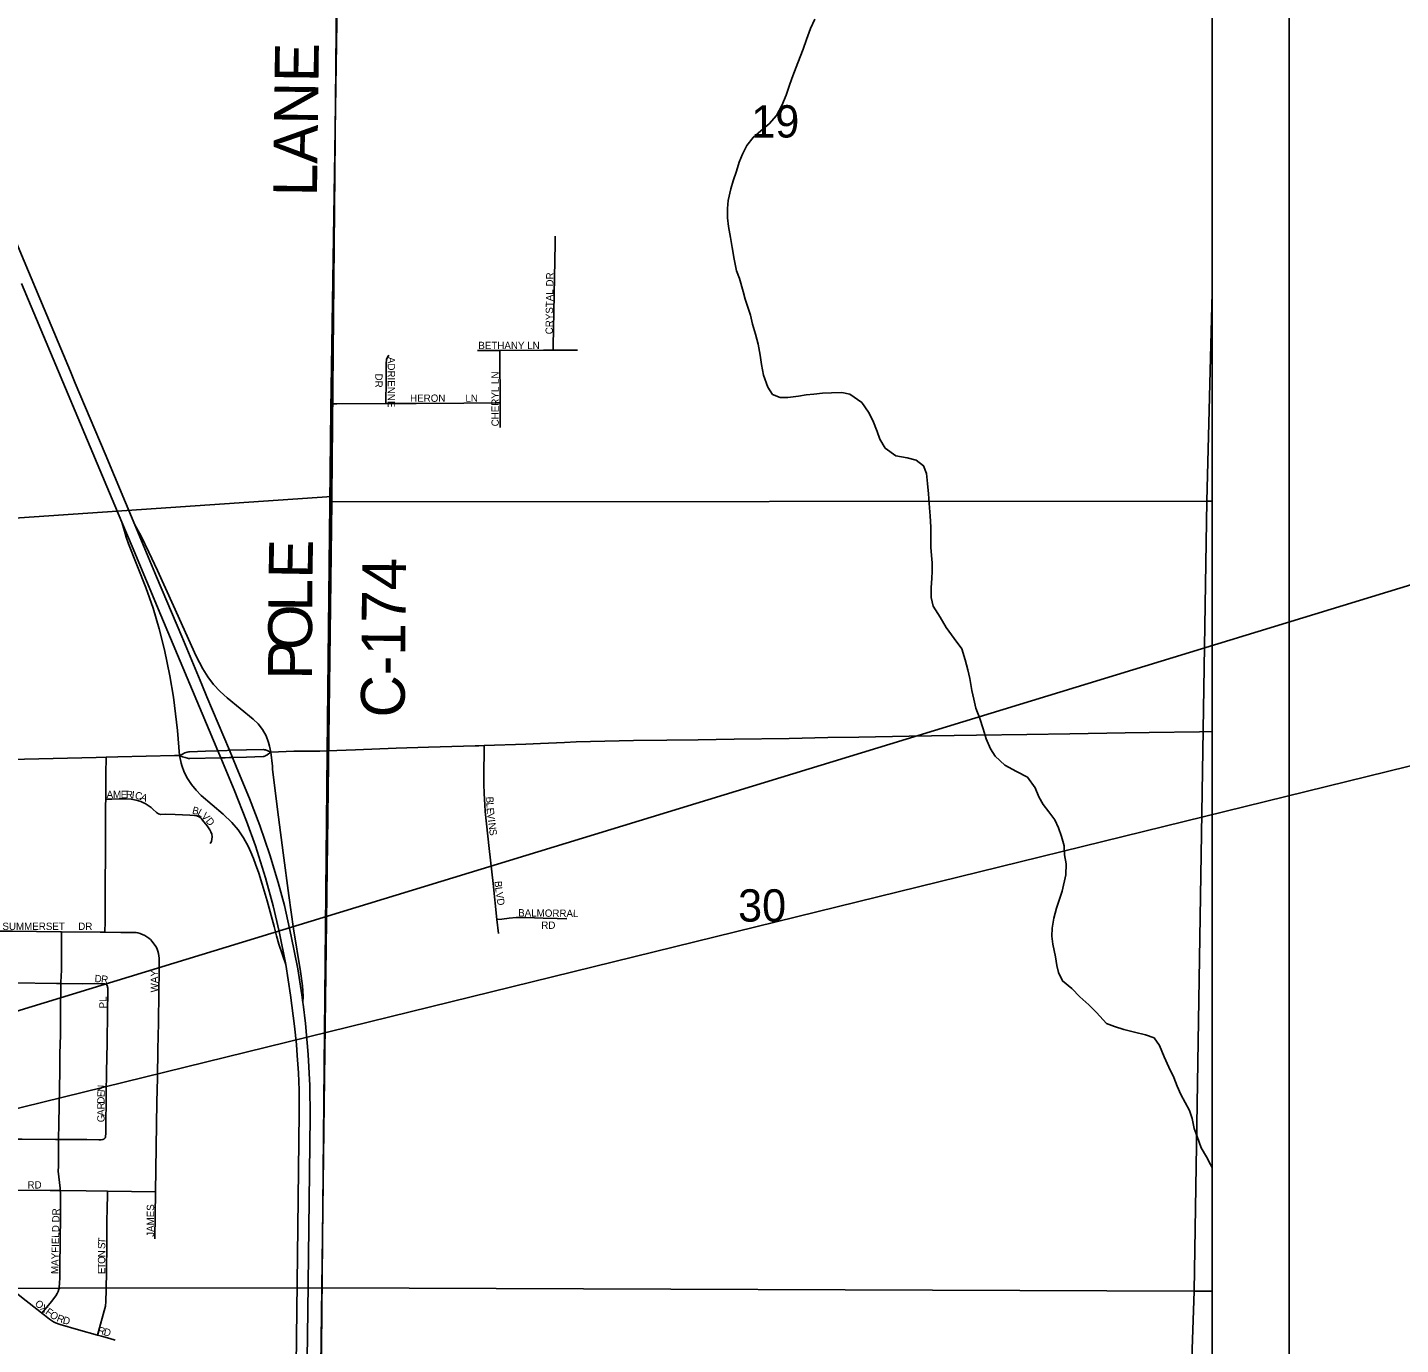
# Model space of a CAD drawing. Extents: x -9.1 to 34, y -3.1 to 22.
# Drawn here: x 7.865 to 9.644, y 18.681 to 20.388 of the extents above; entities that cross this region are included whole.
import ezdxf

# ---------------------------------------------------------------- set-up
doc = ezdxf.new("R2010")
doc.units = 0
for name, color, linetype in [('GM_X_County_Road', 7, 'Continuous'), ('GM_X_County_Road_Text', 7, 'Continuous'), ('GM_X_Interchange_Ramps', 7, 'Continuous'), ('GM_X_Minor_River', 7, 'Continuous'), ('GM_X_Section', 7, 'Continuous'), ('GM_X_Section_Text', 7, 'Continuous'), ('GM_X_State_Route', 7, 'Continuous'), ('GM_X_Township', 7, 'Continuous'), ('GM_X_Township_Subdivision', 7, 'Continuous'), ('GM_X_Township_Subdivision_Text', 7, 'Continuous'), ('GM_X_US_Route', 7, 'Continuous'), ('SH_Data', 7, 'Continuous'), ('SH_Text', 7, 'Continuous')]:
    doc.layers.add(name, color=color, linetype=linetype)

msp = doc.modelspace()

# ---------------------------------------------------------------- linework, layer by layer
at = {"layer": 'GM_X_County_Road'}
for points in [[(8.2593, 19.9003), (8.2605, 19.9991), (8.261, 20.0209), (8.2609, 20.0489), (8.2612, 20.0551), (8.2618, 20.0924), (8.263, 20.1949), (8.2641, 20.2889), (8.2658, 20.4372), (8.2662, 20.4625)], [(8.2539, 19.4505), (8.254, 19.4543), (8.2552, 19.5829), (8.2556, 19.6078), (8.2562, 19.6482), (8.2568, 19.7072), (8.2571, 19.7383), (8.2577, 19.7787), (8.2587, 19.8563), (8.2593, 19.9003)]]:
    msp.add_lwpolyline(points, dxfattribs=at)
at = {"layer": 'GM_X_Interchange_Ramps'}
for points in [[(7.9874, 19.7467), (7.9906, 19.7351), (7.9928, 19.7274), (7.996, 19.7187), (8.0185, 19.662), (8.0277, 19.6355), (8.0357, 19.6086), (8.0425, 19.5813), (8.0495, 19.5477), (8.0541, 19.5201), (8.0594, 19.4767), (8.0622, 19.4446)], [(8.1802, 19.4488), (8.1785, 19.4565), (8.1773, 19.4612), (8.1742, 19.4699), (8.1697, 19.478), (8.164, 19.4853), (8.1573, 19.4917), (8.1405, 19.5055), (8.1237, 19.5191), (8.1146, 19.5275), (8.1062, 19.5365), (8.0987, 19.5463), (8.0921, 19.5568), (8.0835, 19.5733), (8.0542, 19.6382), (8.0336, 19.6841), (8.0224, 19.7081), (8.0125, 19.7287), (8.004, 19.7435)], [(8.222, 19.1242), (8.2223, 19.1327), (8.2214, 19.1459), (8.219, 19.1647), (8.2096, 19.2198), (8.2038, 19.2629), (8.1964, 19.3184), (8.1901, 19.3646), (8.1827, 19.4263), (8.1823, 19.4306), (8.1802, 19.4488)], [(8.0622, 19.4446), (8.0637, 19.4368), (8.0642, 19.4345), (8.065, 19.4317), (8.0682, 19.4229), (8.0724, 19.4146), (8.0776, 19.4067), (8.0835, 19.3994), (8.0901, 19.3927), (8.1187, 19.3685), (8.1298, 19.3575), (8.1378, 19.348), (8.1449, 19.3377), (8.151, 19.3269), (8.1544, 19.3193), (8.1578, 19.3111), (8.1605, 19.3038), (8.1647, 19.292), (8.1692, 19.278), (8.1758, 19.2563), (8.1848, 19.2231), (8.1876, 19.211), (8.1906, 19.2001), (8.1996, 19.1737)]]:
    msp.add_lwpolyline(points, dxfattribs=at)
at = {"layer": 'GM_X_Minor_River'}
for points in [[(8.8851, 20.3984), (8.8798, 20.3863), (8.8744, 20.3723), (8.8702, 20.3595), (8.8664, 20.3496), (8.861, 20.3364), (8.8568, 20.325), (8.853, 20.3144), (8.848, 20.3), (8.8426, 20.2868), (8.8358, 20.2736), (8.8259, 20.263), (8.8152, 20.2539), (8.8053, 20.2452), (8.7973, 20.2347), (8.7916, 20.2237), (8.787, 20.2131), (8.7836, 20.2017), (8.7793, 20.1889), (8.7763, 20.1786), (8.7728, 20.1635), (8.772, 20.1533), (8.7723, 20.1411), (8.7734, 20.1298), (8.776, 20.1157), (8.7783, 20.1025), (8.7808, 20.0877), (8.7838, 20.0725), (8.7876, 20.0626), (8.7924, 20.0456), (8.7951, 20.0357)], [(8.7951, 20.0357), (8.7984, 20.0254), (8.8018, 20.0148), (8.8044, 20.0031), (8.8085, 19.9902), (8.8119, 19.9776), (8.8145, 19.9632), (8.8163, 19.9511), (8.8189, 19.9374), (8.8242, 19.9219), (8.8306, 19.9124), (8.8404, 19.9082), (8.8503, 19.9085), (8.8639, 19.91), (8.8742, 19.9118), (8.884, 19.9126), (8.895, 19.914), (8.9068, 19.9144), (8.9201, 19.9147), (8.9307, 19.9128), (8.9462, 19.9017), (8.9548, 19.8895), (8.9605, 19.8785), (8.9661, 19.8641), (8.9695, 19.8542), (8.9763, 19.8428), (8.9903, 19.8329), (9.0047, 19.8302), (9.0164, 19.8272), (9.0262, 19.8199), (9.03, 19.8097), (9.0314, 19.7968), (9.0325, 19.7835), (9.034, 19.7653), (9.0347, 19.7551), (9.0354, 19.7403), (9.0357, 19.7289), (9.0357, 19.7145), (9.0364, 19.7035), (9.0371, 19.694), (9.0375, 19.6834), (9.037, 19.674), (9.0362, 19.6622), (9.0362, 19.6493), (9.0388, 19.6379), (9.0475, 19.6235), (9.0554, 19.6102), (9.0656, 19.5961), (9.0757, 19.5825), (9.0802, 19.5684), (9.0836, 19.5555), (9.0862, 19.5441), (9.0888, 19.5286), (9.0914, 19.5176), (9.094, 19.5058), (9.0989, 19.4925), (9.1034, 19.4789), (9.1071, 19.466), (9.1128, 19.4531), (9.1188, 19.4436), (9.1316, 19.4318), (9.1468, 19.4238), (9.1608, 19.4165), (9.1706, 19.4024), (9.1755, 19.3911), (9.1811, 19.3812), (9.1883, 19.3717), (9.1962, 19.361), (9.2011, 19.3508), (9.2048, 19.3394), (9.2082, 19.3273), (9.2089, 19.3159), (9.2108, 19.3041), (9.2107, 19.2897), (9.2057, 19.2689), (9.2023, 19.2583), (9.1984, 19.2469), (9.195, 19.2337), (9.193, 19.2208), (9.1922, 19.2106), (9.1937, 19.2), (9.197, 19.1836), (9.1989, 19.1726), (9.2011, 19.1632), (9.2064, 19.1525), (9.2185, 19.1426), (9.2287, 19.132), (9.2404, 19.1213), (9.2502, 19.1114), (9.2631, 19.0974), (9.2737, 19.0935), (9.2858, 19.0897), (9.2994, 19.0862), (9.3138, 19.0828), (9.3248, 19.0785), (9.3319, 19.0687), (9.3379, 19.0539), (9.344, 19.0406), (9.3504, 19.0273), (9.3549, 19.0159), (9.3594, 19.0053)], [(9.3594, 19.0053), (9.365, 18.995), (9.3707, 18.9844), (9.3744, 18.9741), (9.377, 18.9612), (9.3808, 18.951), (9.386, 18.9362), (9.3928, 18.9244), (9.3981, 18.9145), (9.4, 18.9105)]]:
    msp.add_lwpolyline(points, dxfattribs=at)
at = {"layer": 'GM_X_Section'}
for p, q in [((9.4, 20.0439), (9.4, 20.782)), ((9.4, 19.7739), (9.4, 20.0439)), ((9.4, 18.7507), (9.4, 19.7739)), ((9.4, 17.736), (9.4, 18.7507))]:
    msp.add_line(p, q, dxfattribs=at)
for points in [[(9.4, 20.782), (8.2692, 20.7856), (8.2683, 20.7561), (8.2596, 19.7802), (8.2596, 19.773), (9.3932, 19.7739), (9.4, 20.0439)], [(9.4, 20.0439), (9.3932, 19.7739), (9.4, 19.7739)], [(9.4, 19.7739), (9.3932, 19.7739), (9.3766, 18.7507), (9.4, 18.7507)], [(9.4, 18.7507), (9.3766, 18.7507), (9.3419, 17.736), (9.4, 17.736)]]:
    msp.add_lwpolyline(points, dxfattribs=at)
for points in [[(8.2683, 20.7561), (8.2596, 19.7802), (7.2408, 19.7107), (7.2498, 20.7358)], [(8.2596, 19.7802), (8.2596, 19.773), (8.2465, 18.7547), (7.2285, 18.7534), (7.2408, 19.7107)], [(9.3932, 19.7739), (9.3766, 18.7507), (8.2465, 18.7547), (8.2596, 19.773)], [(7.2285, 18.7534), (8.2465, 18.7547), (8.2334, 17.7485), (7.2227, 17.7567)], [(9.3766, 18.7507), (9.3419, 17.736), (8.2334, 17.7485), (8.2465, 18.7547)]]:
    msp.add_lwpolyline(points, close=True, dxfattribs=at)
at = {"layer": 'GM_X_State_Route'}
for points in [[(8.5299, 19.46), (8.5609, 19.4613), (8.5759, 19.4621), (8.6501, 19.4638), (8.6936, 19.4643), (8.734, 19.4649), (8.7806, 19.4655), (8.8521, 19.4667), (8.9019, 19.4677), (8.9423, 19.4684), (9.0076, 19.4695), (9.0946, 19.4707), (9.1599, 19.4716), (9.2158, 19.4726), (9.2873, 19.4737), (9.3184, 19.4741), (9.3837, 19.4751), (9.4, 19.4754)], [(8.0622, 19.4446), (8.0657, 19.4464), (8.069, 19.4478), (8.0719, 19.4489), (8.0737, 19.4492), (8.075, 19.4494), (8.0957, 19.4501), (8.1117, 19.4507), (8.1238, 19.4511), (8.1269, 19.4512), (8.1707, 19.4522), (8.1722, 19.452), (8.1734, 19.4517), (8.1745, 19.4513), (8.1755, 19.451), (8.1802, 19.4488)], [(8.1267, 19.4418), (8.1308, 19.4419), (8.1487, 19.4425), (8.1704, 19.4432), (8.1713, 19.4434), (8.1725, 19.4437), (8.1739, 19.4443), (8.175, 19.4449), (8.1757, 19.4454), (8.1802, 19.4488), (8.2101, 19.4499), (8.244, 19.4502), (8.2539, 19.4505)], [(8.2539, 19.4505), (8.29, 19.4517), (8.3429, 19.4538), (8.3846, 19.4553), (8.4452, 19.457), (8.4499, 19.4572)], [(8.4499, 19.4572), (8.4569, 19.4574), (8.5106, 19.4592), (8.5299, 19.46)], [(7.7873, 19.4379), (7.7905, 19.438), (7.8426, 19.4392), (7.9538, 19.4418), (7.967, 19.4423), (7.9821, 19.4429), (8.0553, 19.4445)], [(8.0553, 19.4445), (8.0622, 19.4446)], [(8.0622, 19.4446), (8.0659, 19.4428), (8.0693, 19.4417), (8.0723, 19.4409), (8.0738, 19.4407), (8.0755, 19.4406), (8.1156, 19.4415), (8.1213, 19.4416), (8.1267, 19.4418)]]:
    msp.add_lwpolyline(points, dxfattribs=at)
at = {"layer": 'GM_X_Township'}
for points in [[(8.2717, 20.9), (8.2689, 20.7443), (8.2697, 20.6456), (8.2583, 19.8928), (8.2535, 19.4485), (8.2445, 18.5434), (8.2345, 17.7477), (8.5348, 17.7425), (9.3398, 17.7284), (9.4, 17.7292)], [(9.4, 17.7292), (9.4, 20.9), (8.2717, 20.9)]]:
    msp.add_lwpolyline(points, dxfattribs=at)
at = {"layer": 'GM_X_Township_Subdivision'}
for points in [[(8.5463, 19.9695), (8.5464, 19.9752), (8.5487, 20.1076), (8.5489, 20.1171)], [(8.4482, 19.9691), (8.477, 19.9692)], [(8.477, 19.9692), (8.5337, 19.9695), (8.5463, 19.9695)], [(8.4773, 19.9014), (8.4771, 19.9629), (8.477, 19.9692)], [(8.5463, 19.9695), (8.5777, 19.9696)], [(8.3293, 19.9005), (8.3296, 19.9309), (8.3299, 19.9542), (8.3301, 19.9559), (8.3304, 19.9576), (8.3316, 19.9607), (8.3332, 19.963)], [(8.2593, 19.9003), (8.266, 19.9003), (8.3293, 19.9005)], [(8.3293, 19.9005), (8.3685, 19.9007), (8.4306, 19.9009), (8.471, 19.9013), (8.4773, 19.9014)], [(8.4774, 19.8693), (8.4773, 19.9014)], [(8.4564, 19.4154), (8.4564, 19.4288), (8.4567, 19.4441), (8.4569, 19.4574)], [(7.9664, 19.3879), (7.9665, 19.3984), (7.9665, 19.4055), (7.9666, 19.4276), (7.9668, 19.4356), (7.967, 19.4423)], [(8.4632, 19.3242), (8.4582, 19.3719), (8.4576, 19.3806), (8.4569, 19.3952), (8.4564, 19.4074), (8.4564, 19.4154)], [(7.9653, 19.2154), (7.9657, 19.2293), (7.9657, 19.2332), (7.9657, 19.262), (7.9658, 19.2722), (7.9658, 19.2866), (7.9659, 19.3086), (7.9661, 19.3498), (7.9662, 19.3609), (7.9663, 19.3797), (7.9664, 19.3879)], [(7.9664, 19.3879), (7.9745, 19.3881), (7.9839, 19.3884), (7.9933, 19.3884), (7.9995, 19.3879), (8.0057, 19.3867), (8.0117, 19.3849), (8.0145, 19.3836), (8.0173, 19.3822), (8.02, 19.3806), (8.0252, 19.377), (8.0275, 19.3749), (8.032, 19.3705), (8.0346, 19.3689), (8.0376, 19.3682), (8.0439, 19.3683), (8.0564, 19.3682), (8.0752, 19.3674), (8.0815, 19.3669), (8.0846, 19.3663), (8.0874, 19.365), (8.0899, 19.3631), (8.092, 19.3609), (8.0978, 19.3534), (8.1013, 19.3482), (8.1027, 19.3454), (8.1037, 19.3424), (8.1042, 19.3393), (8.1041, 19.3362), (8.1033, 19.3332), (8.1019, 19.3304)], [(8.4734, 19.2318), (8.4683, 19.2785), (8.4632, 19.3242)], [(8.4734, 19.2318), (8.4798, 19.2326), (8.4891, 19.2338), (8.4984, 19.2345), (8.5109, 19.2346), (8.5332, 19.2339)], [(8.5332, 19.2339), (8.5515, 19.2332), (8.5632, 19.233), (8.5636, 19.2331), (8.564, 19.2333)], [(7.7817, 19.217), (7.7961, 19.217), (7.8045, 19.2171), (7.8148, 19.217), (7.8458, 19.2167), (7.8769, 19.2165), (7.9079, 19.2162), (7.9092, 19.2162)], [(7.9084, 19.1491), (7.9084, 19.151), (7.9089, 19.1665), (7.9092, 19.1945), (7.9092, 19.2068), (7.9092, 19.2162)], [(7.9092, 19.2162), (7.9591, 19.2156), (7.9653, 19.2154)], [(8.4753, 19.2138), (8.4734, 19.2318)], [(7.9653, 19.2154), (7.9859, 19.2153), (8.0019, 19.2153), (8.0029, 19.2153)], [(8.0355, 19.1654), (8.0358, 19.1757), (8.0356, 19.1819), (8.0354, 19.1849), (8.0349, 19.1879), (8.0341, 19.1908), (8.0331, 19.1937), (8.0318, 19.1964), (8.0302, 19.1989), (8.0265, 19.2037), (8.0243, 19.2059), (8.0221, 19.2079), (8.0196, 19.2096), (8.017, 19.2111), (8.0142, 19.2124), (8.0126, 19.2131), (8.011, 19.2137), (8.0079, 19.2148), (8.0057, 19.2151), (8.0029, 19.2153)], [(8.031, 18.879), (8.0327, 18.9953), (8.0333, 19.0268), (8.0339, 19.0637), (8.0346, 19.098), (8.0351, 19.1378), (8.0355, 19.1654)], [(7.8453, 19.1501), (7.847, 19.1501), (7.9026, 19.1492), (7.9084, 19.1491)], [(7.9052, 18.947), (7.9056, 18.9677), (7.9069, 19.036), (7.9069, 19.0485), (7.907, 19.0578), (7.9077, 19.0826), (7.9077, 19.0981), (7.908, 19.1106), (7.9084, 19.1491)], [(7.9084, 19.1491), (7.9365, 19.1488), (7.9519, 19.1489), (7.9615, 19.1488), (7.9646, 19.1485), (7.9661, 19.1481), (7.9672, 19.1476)], [(7.9648, 18.9481), (7.9653, 18.9486), (7.9657, 18.9493), (7.9659, 18.9502), (7.9662, 18.9515), (7.9664, 18.9545), (7.9664, 18.972), (7.9668, 18.9938), (7.9669, 19.0063), (7.9673, 19.0345), (7.9681, 19.072), (7.9687, 19.1126), (7.9692, 19.1386), (7.9691, 19.1429), (7.9689, 19.1443), (7.9686, 19.1456), (7.968, 19.1468), (7.9672, 19.1476)], [(7.842, 18.9476), (7.8581, 18.9475), (7.9015, 18.947), (7.9052, 18.947)], [(7.905, 18.9129), (7.905, 18.9211), (7.9051, 18.9397), (7.9052, 18.947)], [(7.9052, 18.947), (7.9418, 18.9468), (7.9573, 18.9466), (7.9607, 18.9467), (7.9628, 18.9471), (7.964, 18.9475), (7.9648, 18.9481)], [(7.9075, 18.881), (7.9072, 18.884), (7.9055, 18.8986), (7.9051, 18.9027), (7.9049, 18.9056), (7.905, 18.9129)], [(7.8491, 18.8814), (7.8512, 18.8813), (7.8946, 18.8811), (7.9075, 18.881)], [(7.8837, 18.7218), (7.8881, 18.7273), (7.896, 18.737), (7.9016, 18.7445), (7.9033, 18.7473), (7.9046, 18.7502), (7.9055, 18.7533), (7.9061, 18.7564), (7.9065, 18.7596), (7.9069, 18.7689), (7.907, 18.7814), (7.9075, 18.8158), (7.9079, 18.8467), (7.908, 18.859), (7.908, 18.8684), (7.9079, 18.8778), (7.9075, 18.881)], [(7.9075, 18.881), (7.9411, 18.8806), (7.9687, 18.8802)], [(7.9557, 18.6936), (7.957, 18.6984), (7.9645, 18.7251), (7.9659, 18.7311), (7.9667, 18.7371), (7.967, 18.7524), (7.9673, 18.777), (7.9678, 18.8109), (7.968, 18.8386), (7.9684, 18.8602), (7.9686, 18.8725), (7.9687, 18.8802)], [(7.9687, 18.8802), (8.031, 18.879)], [(8.0299, 18.8181), (8.031, 18.879)], [(7.8837, 18.7218), (7.8808, 18.7241), (7.8596, 18.7412), (7.8343, 18.7613)], [(7.9557, 18.6936), (7.9311, 18.7005), (7.9072, 18.7074), (7.9014, 18.7094), (7.8987, 18.7107), (7.8936, 18.7141), (7.887, 18.7193), (7.8837, 18.7218)], [(7.9786, 18.6871), (7.9718, 18.6891), (7.9611, 18.6921), (7.9557, 18.6936)]]:
    msp.add_lwpolyline(points, dxfattribs=at)
at = {"layer": 'GM_X_US_Route'}
for points in [[(7.9207, 19.9418), (7.8955, 20.0014), (7.8607, 20.0848), (7.8464, 20.1189), (7.8172, 20.1875), (7.7752, 20.2878), (7.7605, 20.3227)], [(8.2128, 18.6185), (8.2154, 18.8328), (8.2169, 18.982), (8.217, 19.0111), (8.2163, 19.0333), (8.2145, 19.056), (8.2134, 19.07), (8.211, 19.0938), (8.206, 19.1339), (8.1996, 19.1737), (8.1996, 19.1738), (8.1912, 19.2165), (8.1833, 19.2498), (8.1734, 19.2858), (8.1604, 19.3274), (8.1489, 19.3596), (8.1328, 19.4), (8.1156, 19.4415), (8.1117, 19.4507), (8.1006, 19.4775), (8.0379, 19.6264), (8.0006, 19.7152), (7.9874, 19.7467), (7.8572, 20.0561)], [(8.1364, 19.4282), (8.1308, 19.4419), (8.1269, 19.4512), (8.0976, 19.5205), (8.091, 19.5364), (8.0651, 19.5987), (8.0323, 19.6761), (8.004, 19.7435), (7.9655, 19.8353), (7.927, 19.9269), (7.9207, 19.9418)], [(8.2222, 19.1222), (8.222, 19.1242), (8.2207, 19.1343), (8.2153, 19.168), (8.2069, 19.2106), (8.198, 19.25), (8.19, 19.28), (8.1791, 19.3156), (8.1661, 19.3538), (8.1528, 19.3886), (8.1364, 19.4282)], [(8.2176, 17.8023), (8.2192, 17.939), (8.2198, 17.9855), (8.2201, 18.0166), (8.223, 18.2465), (8.2235, 18.2962), (8.2251, 18.4174), (8.2262, 18.5262), (8.2265, 18.5511), (8.2266, 18.5664), (8.2268, 18.6005), (8.2271, 18.6316), (8.2282, 18.7248), (8.2315, 18.9764), (8.2308, 19.0168), (8.2288, 19.0571), (8.2253, 19.0973), (8.2222, 19.1222)]]:
    msp.add_lwpolyline(points, dxfattribs=at)
at = {"layer": 'SH_Data'}
for p, q in [((9.5, 21), (9.5, 14)), ((9.4, 20.9), (9.4, 14.1))]:
    msp.add_line(p, q, dxfattribs=at)
at = {"layer": 'SH_Text'}
msp.add_lwpolyline([(9.6799, 19.6726), (5.7467, 18.4697), (9.6799, 19.4366)], close=True, dxfattribs=at)

# ---------------------------------------------------------------- texts
at = {"layer": 'GM_X_County_Road_Text'}
for s, height, rotation, p in [('LANE', 0.05682, 89.2592, (8.2401, 20.1687)), ('E', 0.0568, 88.92, (8.2342, 19.6733)), ('C-174', 0.05682, 89.4498, (8.3537, 19.4935)), ('L', 0.0568, 89.6871, (8.2339, 19.631)), ('O', 0.0568, 89.7128, (8.2337, 19.581)), ('P', 0.0568, 89.7101, (8.2335, 19.5427))]:
    msp.add_text(s, height=height, rotation=rotation, dxfattribs=at).set_placement(p)
at = {"layer": 'GM_X_Section_Text'}
for s, p in [('19', (8.8029, 20.2451)), ('30', (8.7858, 19.2293))]:
    msp.add_text(s, height=0.04186, rotation=0, dxfattribs=at).set_placement(p)
at = {"layer": 'GM_X_Township_Subdivision_Text'}
for s, rotation, p in [('CRYSTAL DR', 89.3341, (8.5457, 19.9901)), ('BETHANY LN', 0, (8.4492, 19.971)), ('ADRIENNE', 270, (8.3318, 19.9609)), ('DR', 270, (8.3157, 19.9393)), ('CHERYL LN', 90, (8.4757, 19.8709)), ('HERON', 0, (8.3608, 19.9027)), ('LN', 0, (8.4325, 19.9027)), ('A', 359.8688, (7.9675, 19.3894)), ('M', 359.8543, (7.9758, 19.3894)), ('E', 359.8574, (7.9858, 19.3893)), ('R', 358.98, (7.9925, 19.3893)), ('I', 353.4281, (7.9997, 19.3892)), ('C', 346.8707, (8.0036, 19.3888)), ('A', 338.2798, (8.0105, 19.3872)), ('B', 346.594, (8.0778, 19.3694)), ('B', 272.5507, (8.4593, 19.391)), ('L', 272.5785, (8.4596, 19.3835)), ('E', 274.3811, (8.4599, 19.3765)), ('L', 331.2108, (8.0844, 19.3679)), ('V', 314.382, (8.0897, 19.3651)), ('D', 310.7767, (8.0954, 19.3592)), ('V', 277.1547, (8.4605, 19.3694)), ('I', 277.4895, (8.4615, 19.361)), ('N', 277.4953, (8.4621, 19.3569)), ('S', 277.4989, (8.4632, 19.3486)), ('B', 275.1549, (8.4701, 19.2815)), ('L', 277.899, (8.4709, 19.2736)), ('V', 278.1396, (8.4718, 19.2669)), ('D', 278.1363, (8.473, 19.2587)), ('BALMORRAL', 359.3493, (8.5008, 19.236)), ('SUMMERSET', 0, (7.8325, 19.2185)), ('DR', 0, (7.9308, 19.2185)), ('RD', 0, (8.5308, 19.2199)), ('WAY', 90, (8.0341, 19.1376)), ('D', 355.9097, (7.9517, 19.151)), ('R', 352.6461, (7.9599, 19.1505)), ('PL', 90, (7.9674, 19.1168)), ('E', 88.6614, (7.9649, 19.0017)), ('N', 86.3691, (7.9651, 19.0083)), ('D', 89.9812, (7.9649, 18.9934)), ('R', 89.9514, (7.9649, 18.9859)), ('A', 89.9781, (7.9649, 18.9776)), ('G', 89.9781, (7.9649, 18.9693)), ('RD', 0, (7.865, 18.8835)), ('JAMES', 90, (8.0291, 18.8209)), ('MAYFIELD DR', 88.8081, (7.905, 18.7726)), ('S', 88.7433, (7.9657, 18.805)), ('T', 85.7061, (7.9659, 18.8116)), ('O', 89.9703, (7.9657, 18.7859)), ('N', 89.9563, (7.9657, 18.7943)), ('T', 89.9453, (7.9657, 18.7793)), ('E', 89.9727, (7.9657, 18.7726)), ('O', 318.3864, (7.8737, 18.7331)), ('X', 322.2153, (7.8805, 18.7271)), ('F', 324.4384, (7.8874, 18.7218)), ('O', 324.901, (7.8929, 18.7178)), ('R', 339.8554, (7.9021, 18.7118)), ('D', 345.4319, (7.9101, 18.7089)), ('R', 345.1155, (7.9554, 18.6957)), ('D', 347.3895, (7.9631, 18.6936))]:
    msp.add_text(s, height=0.00947, rotation=rotation, dxfattribs=at).set_placement(p)

doc.saveas('drawing.dxf')
